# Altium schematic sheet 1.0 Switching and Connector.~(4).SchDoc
size A4; SheetNumber: 1; SheetTotal: 1
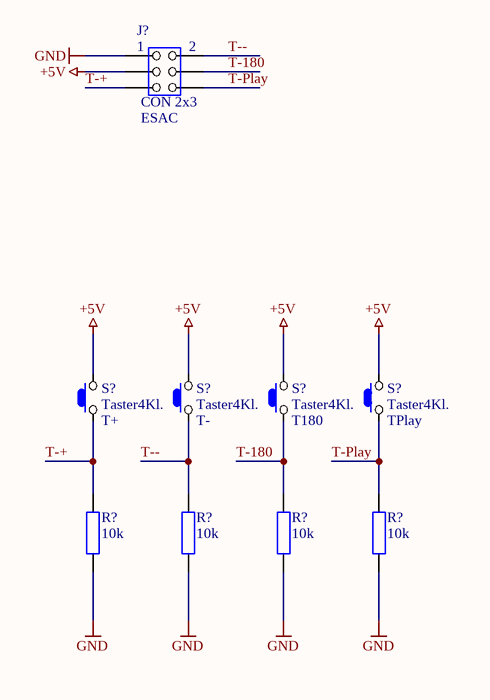
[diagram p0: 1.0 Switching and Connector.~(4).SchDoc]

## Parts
(Parts that share a designator on the sheet are numbered #1, #2 ... from top to bottom, then left to right.)
J?  CON 2x3  Use: ESAC  [J_2x3]
R?#1  10k  [R_SMD_0805]
R?#2  10k  [R_SMD_0805]
R?#3  10k  [R_SMD_0805]
R?#4  10k  [R_SMD_0805]
S?#1  Taster4Kl.  Use: T+  [S_THT_Taster4kl.]
S?#2  Taster4Kl.  Use: T-  [S_THT_Taster4kl.]
S?#3  Taster4Kl.  Use: T180  [S_THT_Taster4kl.]
S?#4  Taster4Kl.  Use: TPlay  [S_THT_Taster4kl.]

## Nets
+5V: J?.3 S?#1.2 S?#2.2 S?#3.2 S?#4.2
GND: J?.1 R?#1.1 R?#2.1 R?#3.1 R?#4.1
T-180: J?.4 R?#3.2 S?#3.1
T-+: J?.5 R?#1.2 S?#1.1
T--: J?.2 R?#2.2 S?#2.1
T-Play: J?.6 R?#4.2 S?#4.1

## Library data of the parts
J? = J_THT_IDC 2x3: Stecker
R?#1-R?#4 = R_SMD_Widerstand: Widerstand SMD
S?#1-S?#4 = S_THT_Taster: Taster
